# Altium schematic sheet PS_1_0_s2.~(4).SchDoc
size A4
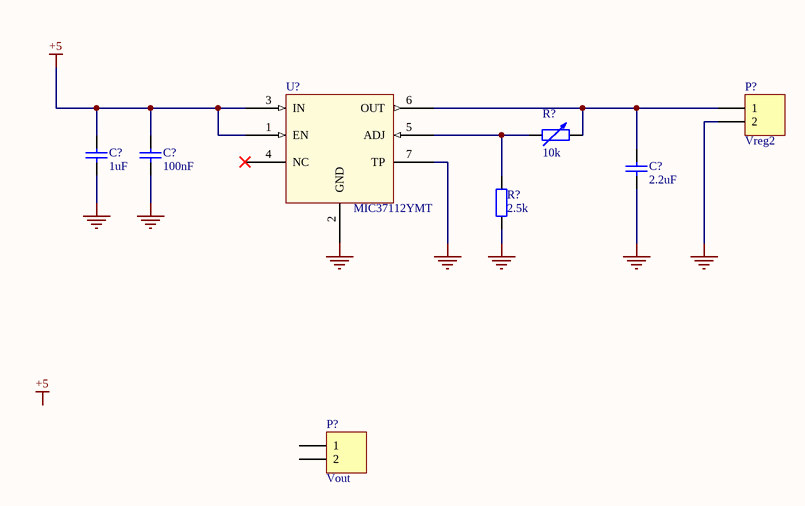
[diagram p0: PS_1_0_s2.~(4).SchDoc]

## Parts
(Parts that share a designator on the sheet are numbered #1, #2 ... from top to bottom, then left to right.)
C?#1  1uF  [0603]
C?#2  100nF  [0603]
C?#3  2.2uF  [0603]
P?#1  Vreg2  [HDR1X2]
P?#2  Vout  [HDR1X2]
R?#1  10k  [AXIAL-0.6]
R?#2  2.5k  [0603]
U?  MIC37112YMT

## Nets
+5: C?#1.1 C?#2.1 U?.1(EN) U?.3(IN)
GND: C?#1.2 C?#2.2 C?#3.2 P?#1.2 R?#2.1 U?.2(GND) U?.7(TP)
NetC?#3_1: C?#3.1 P?#1.1 R?#1.2 U?.6(OUT)
NetR?#1_1: R?#1.1 R?#2.2 U?.5(ADJ)

Not connected (* = marked no-connect by the designer): P?#2 1 2; U? 4(NC)*

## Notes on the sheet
- Labels drawn without touching a wire or pin: +5

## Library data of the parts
C?#1-C?#3 = Cap Semi: Capacitor (Semiconductor SIM Model)
P?#1 P?#2 = Header 2: Header, 2-Pin
R?#1 = Res Adj2: Variable Resistor; Set Position: 0.5
R?#2 = Res2: Resistor
U? = MIC37112YMT: LDO, 1A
